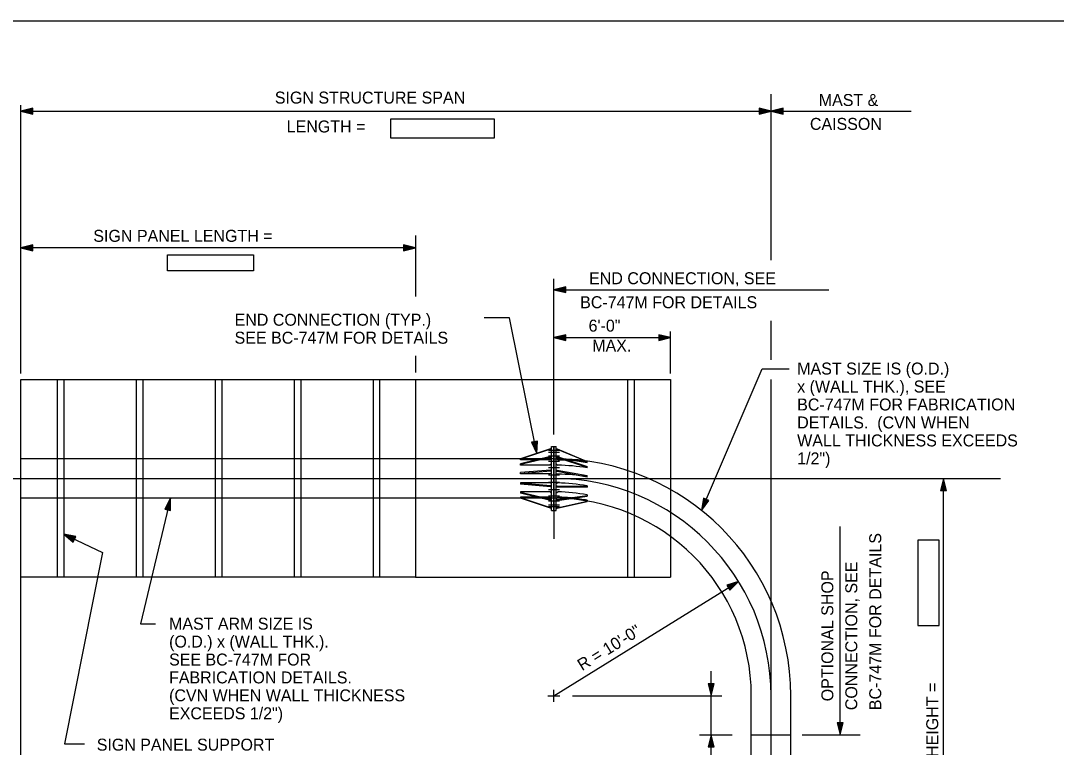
# Model space of a CAD drawing. Extents: x 640117 to 642655, y 297247 to 298435.
# Drawn here: x 640465.5 to 640724.9, y 297644.5 to 297826.5 of the extents above; entities that cross this region are included whole.
import ezdxf

# ---------------------------------------------------------------- set-up
doc = ezdxf.new("R2010")
doc.units = 0
for name, color, linetype in [('10', 7, 'Continuous'), ('2', 7, 'Continuous'), ('48', 7, 'Continuous'), ('49', 7, 'Continuous'), ('50', 7, 'Continuous'), ('52', 7, 'Continuous'), ('53', 7, 'Continuous'), ('55', 7, 'Continuous')]:
    doc.layers.add(name, color=color, linetype=linetype)

msp = doc.modelspace()

# ---------------------------------------------------------------- linework, layer by layer
at = {"layer": '10'}
msp.add_lwpolyline([(640690.25, 297675.07), (640695.62, 297675.07), (640695.62, 297696.4), (640690.25, 297696.4)], close=True, dxfattribs=at)
at = {"layer": '2'}
msp.add_line((640157.46, 297826.46), (640943.46, 297826.46), dxfattribs=at)
for points in [[(640558.23, 297801.89), (640584.08, 297801.89), (640584.08, 297797.09), (640558.23, 297797.09)], [(640502.27, 297767.87), (640523.82, 297767.87), (640523.82, 297763.87), (640502.27, 297763.87)]]:
    msp.add_lwpolyline(points, close=True, dxfattribs=at)
at = {"layer": '48'}
for p, q in [((640597.69, 297718.9), (640600.47, 297718.9)), ((640597.69, 297718.42), (640600.47, 297718.42)), ((640597.69, 297717.49), (640600.47, 297717.49)), ((640597.69, 297716.18), (640600.47, 297716.18)), ((640597.69, 297714.57), (640600.47, 297714.57)), ((640597.69, 297712.78), (640600.47, 297712.78)), ((640597.69, 297710.92), (640600.47, 297710.92)), ((640597.69, 297709.13), (640600.47, 297709.13)), ((640597.69, 297707.52), (640600.47, 297707.52)), ((640597.69, 297706.21), (640600.47, 297706.21)), ((640597.69, 297705.28), (640600.47, 297705.28)), ((640597.69, 297704.8), (640600.47, 297704.8))]:
    msp.add_line(p, q, dxfattribs=at)
at = {"layer": '49'}
for p, q in [((640465.5, 297736.59), (640564.44, 297736.59)), ((640465.5, 297687.12), (640465.5, 297736.59)), ((640474.63, 297736.59), (640474.63, 297687.12)), ((640476.28, 297736.59), (640476.28, 297687.12)), ((640494.42, 297736.59), (640494.42, 297687.12)), ((640496.06, 297736.59), (640496.06, 297687.12)), ((640514.2, 297736.59), (640514.2, 297687.12)), ((640515.85, 297736.59), (640515.85, 297687.12)), ((640533.99, 297736.59), (640533.99, 297687.12)), ((640535.64, 297736.59), (640535.64, 297687.12)), ((640553.78, 297736.59), (640553.78, 297687.12)), ((640555.43, 297736.59), (640555.43, 297687.12)), ((640564.44, 297736.59), (640564.44, 297687.12)), ((640564.44, 297736.59), (640628.33, 297736.59)), ((640617.56, 297736.59), (640617.56, 297687.12)), ((640619.21, 297736.59), (640619.21, 297687.12)), ((640628.33, 297736.59), (640628.33, 297687.12)), ((640564.44, 297687.12), (640465.5, 297687.12)), ((640564.44, 297687.12), (640628.33, 297687.12))]:
    msp.add_line(p, q, dxfattribs=at)
at = {"layer": '50'}
for p, q in [((640653.49, 297766.52), (640653.49, 297808.07)), ((640653.49, 297741.55), (640653.49, 297751.3)), ((640653.49, 297531.9), (640653.49, 297736.65)), ((640599.07, 297719.88), (640599.07, 297696.76)), ((640196.72, 297711.85), (640710.96, 297711.85))]:
    msp.add_line(p, q, dxfattribs=at)
msp.add_arc((640599.07, 297657.43), 54.42, 0, 89.9997, dxfattribs=at)
at = {"layer": '52'}
for p, q in [((640465.5, 297738.09), (640465.5, 297805.35)), ((640468.5, 297804.6), (640465.5, 297803.85)), ((640465.5, 297803.85), (640653.49, 297803.85)), ((640465.5, 297803.85), (640468.5, 297803.1)), ((640468.33, 297804.37), (640466.24, 297803.85)), ((640466.24, 297803.85), (640468.33, 297803.32)), ((640468.15, 297804.14), (640466.97, 297803.85)), ((640466.97, 297803.85), (640468.15, 297803.55)), ((640468.08, 297803.94), (640467.7, 297803.85)), ((640467.7, 297803.85), (640468.06, 297803.76)), ((640468.15, 297803.55), (640468.15, 297804.14)), ((640468.33, 297803.32), (640468.33, 297804.37)), ((640468.5, 297803.1), (640468.5, 297804.6)), ((640653.49, 297803.85), (640650.49, 297804.6)), ((640650.49, 297804.6), (640650.49, 297803.1)), ((640650.49, 297803.1), (640653.49, 297803.85)), ((640652.76, 297803.85), (640650.67, 297804.37)), ((640650.67, 297804.37), (640650.67, 297803.32)), ((640650.67, 297803.32), (640652.76, 297803.85)), ((640652.03, 297803.85), (640650.85, 297804.14)), ((640650.85, 297804.14), (640650.85, 297803.55)), ((640650.85, 297803.55), (640652.03, 297803.85)), ((640650.92, 297803.75), (640651.29, 297803.85)), ((640651.29, 297803.85), (640650.94, 297803.94)), ((640656.49, 297804.6), (640653.49, 297803.85)), ((640653.49, 297803.85), (640656.49, 297803.1)), ((640656.31, 297804.37), (640654.22, 297803.85)), ((640654.22, 297803.85), (640656.31, 297803.32)), ((640656.14, 297804.14), (640654.96, 297803.85)), ((640654.96, 297803.85), (640656.14, 297803.55)), ((640656.07, 297803.94), (640655.69, 297803.85)), ((640655.69, 297803.85), (640656.05, 297803.76)), ((640656.14, 297803.55), (640656.14, 297804.14)), ((640656.31, 297803.32), (640656.31, 297804.37)), ((640656.49, 297803.1), (640656.49, 297804.6)), ((640564.44, 297772.65), (640564.44, 297757.39)), ((640468.5, 297770.32), (640465.5, 297769.57)), ((640564.44, 297769.57), (640465.5, 297769.57)), ((640465.5, 297769.57), (640468.5, 297768.82)), ((640468.33, 297770.1), (640466.24, 297769.57)), ((640466.24, 297769.57), (640468.33, 297769.05)), ((640468.15, 297769.87), (640466.97, 297769.57)), ((640466.97, 297769.57), (640468.15, 297769.28)), ((640468.08, 297769.67), (640467.7, 297769.57)), ((640467.7, 297769.57), (640468.06, 297769.48)), ((640468.15, 297769.28), (640468.15, 297769.87)), ((640468.33, 297769.05), (640468.33, 297770.1)), ((640468.5, 297768.82), (640468.5, 297770.32)), ((640564.44, 297769.57), (640561.44, 297770.32)), ((640561.44, 297770.32), (640561.44, 297768.82)), ((640561.44, 297768.82), (640564.44, 297769.57)), ((640563.71, 297769.57), (640561.62, 297770.1)), ((640561.62, 297770.1), (640561.62, 297769.05)), ((640561.62, 297769.05), (640563.71, 297769.57)), ((640562.98, 297769.57), (640561.8, 297769.87)), ((640561.8, 297769.87), (640561.8, 297769.28)), ((640561.8, 297769.28), (640562.98, 297769.57)), ((640561.87, 297769.48), (640562.25, 297769.57)), ((640562.25, 297769.57), (640561.89, 297769.66)), ((640599.07, 297722.88), (640599.07, 297761.86)), ((640602.07, 297759.87), (640599.07, 297759.12)), ((640601.9, 297759.64), (640599.81, 297759.12)), ((640601.72, 297759.42), (640600.54, 297759.12)), ((640601.65, 297759.21), (640601.27, 297759.12)), ((640601.72, 297758.83), (640601.72, 297759.42)), ((640601.9, 297758.6), (640601.9, 297759.64)), ((640602.07, 297758.37), (640602.07, 297759.87)), ((640599.07, 297759.12), (640602.07, 297758.37)), ((640599.81, 297759.12), (640601.9, 297758.6)), ((640600.54, 297759.12), (640601.72, 297758.83)), ((640601.27, 297759.12), (640601.63, 297759.03)), ((640602.07, 297747.85), (640599.07, 297747.11)), ((640599.07, 297747.11), (640628.33, 297747.11)), ((640599.07, 297747.11), (640602.07, 297746.36)), ((640601.9, 297747.63), (640599.81, 297747.11)), ((640599.81, 297747.11), (640601.9, 297746.58)), ((640601.72, 297747.4), (640600.54, 297747.11)), ((640600.54, 297747.11), (640601.72, 297746.81)), ((640601.65, 297747.2), (640601.27, 297747.11)), ((640601.27, 297747.11), (640601.63, 297747.02)), ((640601.72, 297746.81), (640601.72, 297747.4)), ((640601.9, 297746.58), (640601.9, 297747.63)), ((640602.07, 297746.36), (640602.07, 297747.85)), ((640628.33, 297747.11), (640625.33, 297747.85)), ((640625.33, 297747.85), (640625.33, 297746.36)), ((640625.33, 297746.36), (640628.33, 297747.11)), ((640627.6, 297747.11), (640625.51, 297747.63)), ((640625.51, 297747.63), (640625.51, 297746.58)), ((640625.51, 297746.58), (640627.6, 297747.11)), ((640626.87, 297747.11), (640625.69, 297747.4)), ((640625.69, 297747.4), (640625.69, 297746.81)), ((640625.69, 297746.81), (640626.87, 297747.11)), ((640625.76, 297747.01), (640626.14, 297747.11)), ((640626.14, 297747.11), (640625.78, 297747.2)), ((640628.33, 297738.09), (640628.33, 297748.61)), ((640564.44, 297742.56), (640564.44, 297738.42)), ((640594.96, 297721.22), (640593.49, 297720.92)), ((640593.49, 297720.92), (640594.82, 297718.13)), ((640594.77, 297721), (640593.75, 297720.79)), ((640593.75, 297720.79), (640594.67, 297718.84)), ((640594.59, 297720.78), (640594.01, 297720.66)), ((640594.01, 297720.66), (640594.53, 297719.56)), ((640594.22, 297720.63), (640594.38, 297720.28)), ((640594.38, 297720.28), (640594.4, 297720.65)), ((640594.53, 297719.56), (640594.59, 297720.78)), ((640594.67, 297718.84), (640594.77, 297721)), ((640594.82, 297718.13), (640594.96, 297721.22)), ((640696.66, 297711.85), (640695.91, 297708.85)), ((640696.66, 297711.12), (640696.13, 297709.03)), ((640696.66, 297710.39), (640696.36, 297709.21)), ((640696.66, 297588.17), (640696.66, 297711.85)), ((640697.4, 297708.85), (640696.66, 297711.85)), ((640697.18, 297709.03), (640696.66, 297711.12)), ((640696.95, 297709.21), (640696.66, 297710.39)), ((640695.91, 297708.85), (640697.4, 297708.85)), ((640696.13, 297709.03), (640697.18, 297709.03)), ((640696.36, 297709.21), (640696.95, 297709.21)), ((640696.66, 297709.65), (640696.57, 297709.3)), ((640696.75, 297709.28), (640696.66, 297709.65)), ((640503.03, 297706.9), (640501.61, 297704.16)), ((640502.86, 297706.19), (640501.87, 297704.28)), ((640502.69, 297705.48), (640502.13, 297704.4)), ((640502.52, 297704.77), (640502.35, 297704.44)), ((640502.53, 297704.38), (640502.52, 297704.77)), ((640502.71, 297704.26), (640502.69, 297705.48)), ((640502.89, 297704.04), (640502.86, 297706.19)), ((640503.07, 297703.81), (640503.03, 297706.9)), ((640636.55, 297706.92), (640636.06, 297703.87)), ((640636.06, 297703.87), (640637.93, 297706.33)), ((640636.69, 297706.67), (640636.35, 297704.54)), ((640636.35, 297704.54), (640637.65, 297706.26)), ((640637.93, 297706.33), (640636.55, 297706.92)), ((640636.83, 297706.42), (640636.64, 297705.22)), ((640636.64, 297705.22), (640637.37, 297706.18)), ((640637.65, 297706.26), (640636.69, 297706.67)), ((640637.37, 297706.18), (640636.83, 297706.42)), ((640636.99, 297706.27), (640636.92, 297705.89)), ((640636.92, 297705.89), (640637.15, 297706.18)), ((640501.61, 297704.16), (640503.07, 297703.81)), ((640501.87, 297704.28), (640502.89, 297704.04)), ((640502.13, 297704.4), (640502.71, 297704.26)), ((640476.28, 297697.9), (640478.67, 297695.94)), ((640479.31, 297697.3), (640476.28, 297697.9)), ((640476.94, 297697.59), (640478.61, 297696.22)), ((640479.05, 297697.17), (640476.94, 297697.59)), ((640478.79, 297697.04), (640477.6, 297697.27)), ((640477.6, 297697.27), (640478.54, 297696.5)), ((640478.26, 297696.96), (640478.55, 297696.73)), ((640478.64, 297696.88), (640478.26, 297696.96)), ((640478.54, 297696.5), (640478.79, 297697.04)), ((640478.61, 297696.22), (640479.05, 297697.17)), ((640478.67, 297695.94), (640479.31, 297697.3)), ((640465.5, 297626.36), (640465.5, 297687.12)), ((640599.07, 297657.43), (640645.35, 297686.07)), ((640645.35, 297686.07), (640642.4, 297685.13)), ((640642.4, 297685.13), (640643.19, 297683.86)), ((640644.72, 297685.69), (640642.67, 297685.03)), ((640642.67, 297685.03), (640643.22, 297684.14)), ((640644.1, 297685.3), (640642.94, 297684.93)), ((640642.94, 297684.93), (640643.25, 297684.43)), ((640643.48, 297684.91), (640643.13, 297684.8)), ((640643.19, 297683.86), (640645.35, 297686.07)), ((640643.21, 297684.64), (640643.48, 297684.91)), ((640643.22, 297684.14), (640644.72, 297685.69)), ((640643.25, 297684.43), (640644.1, 297685.3)), ((640638.5, 297626.19), (640638.5, 297663.57)), ((640599.07, 297655.93), (640599.07, 297658.93)), ((640637.75, 297660.43), (640638.5, 297657.43)), ((640639.25, 297660.43), (640637.75, 297660.43)), ((640637.98, 297660.26), (640638.5, 297658.17)), ((640639.02, 297660.26), (640637.98, 297660.26)), ((640638.21, 297660.08), (640638.5, 297658.9)), ((640638.8, 297660.08), (640638.21, 297660.08)), ((640638.41, 297660.01), (640638.5, 297659.63)), ((640638.5, 297657.43), (640639.25, 297660.43)), ((640638.5, 297658.17), (640639.02, 297660.26)), ((640638.5, 297658.9), (640638.8, 297660.08)), ((640638.5, 297659.63), (640638.59, 297659.99)), ((640597.57, 297657.43), (640600.57, 297657.43)), ((640603.75, 297657.43), (640641.12, 297657.43)), ((640670.09, 297650.68), (640670.84, 297647.68)), ((640671.59, 297650.68), (640670.09, 297650.68)), ((640670.32, 297650.5), (640670.84, 297648.41)), ((640671.36, 297650.5), (640670.32, 297650.5)), ((640670.54, 297650.33), (640670.84, 297649.15)), ((640671.13, 297650.33), (640670.54, 297650.33)), ((640670.75, 297650.25), (640670.84, 297649.88)), ((640670.84, 297647.68), (640671.59, 297650.68)), ((640670.84, 297648.41), (640671.36, 297650.5)), ((640670.84, 297649.15), (640671.13, 297650.33)), ((640670.84, 297649.88), (640670.93, 297650.24)), ((640635.6, 297647.68), (640643.75, 297647.68)), ((640638.5, 297647.68), (640637.75, 297644.68)), ((640638.5, 297647.68), (640638.5, 297647.68)), ((640639.25, 297644.68), (640638.5, 297647.68)), ((640661.31, 297647.68), (640675.81, 297647.68)), ((640638.5, 297646.95), (640637.98, 297644.86)), ((640638.5, 297646.21), (640638.21, 297645.03)), ((640638.21, 297645.03), (640638.8, 297645.03)), ((640638.5, 297645.48), (640638.41, 297645.12)), ((640639.02, 297644.86), (640638.5, 297646.95)), ((640638.8, 297645.03), (640638.5, 297646.21)), ((640638.59, 297645.11), (640638.5, 297645.48)), ((640637.75, 297644.68), (640639.25, 297644.68)), ((640637.98, 297644.86), (640639.02, 297644.86))]:
    msp.add_line(p, q, dxfattribs=at)
for points in [[(640653.49, 297803.85), (640688.61, 297803.85)], [(640599.07, 297759.12), (640667.98, 297759.12)], [(640594.82, 297718.13), (640587.98, 297752.1), (640581.62, 297752.1)], [(640636.06, 297703.87), (640651.22, 297739.32), (640658.03, 297739.32)], [(640503.03, 297706.9), (640495.54, 297675.43), (640499.29, 297675.43)], [(640670.84, 297647.68), (640670.84, 297699.86)], [(640476.28, 297697.9), (640485.97, 297693.32), (640476.48, 297645.39), (640481.47, 297645.39)]]:
    msp.add_lwpolyline(points, dxfattribs=at)
at = {"layer": '55'}
for p, q in [((640598.26, 297719.25), (640590.74, 297716.8)), ((640598.26, 297719.17), (640590.74, 297716.72)), ((640598.46, 297719.25), (640598.26, 297719.25)), ((640598.46, 297719.17), (640598.26, 297719.17)), ((640598.46, 297719.88), (640599.68, 297719.88)), ((640598.46, 297703.82), (640598.46, 297719.88)), ((640599.07, 297703.82), (640599.07, 297719.88)), ((640599.68, 297703.82), (640599.68, 297719.88)), ((640599.68, 297719.25), (640599.89, 297719.25)), ((640599.68, 297719.17), (640599.89, 297719.17)), ((640599.89, 297719.25), (640607.4, 297716.14)), ((640599.89, 297719.17), (640607.4, 297716.06)), ((640564.44, 297716.8), (640465.5, 297716.8)), ((640599.07, 297716.8), (640564.44, 297716.8)), ((640598.26, 297717.35), (640590.74, 297715.55)), ((640598.26, 297717.13), (640590.74, 297715.33)), ((640590.74, 297716.52), (640590.74, 297716.8)), ((640590.74, 297716.73), (640598.46, 297716.73)), ((640594.81, 297716.52), (640590.74, 297716.52)), ((640590.74, 297715.19), (640590.74, 297715.55)), ((640598.06, 297715.19), (640590.74, 297715.19)), ((640598.06, 297716.52), (640594.81, 297716.52)), ((640598.46, 297716.91), (640598.06, 297716.52)), ((640598.46, 297715.48), (640598.06, 297715.19)), ((640598.46, 297717.35), (640598.26, 297717.35)), ((640598.46, 297717.13), (640598.26, 297717.13)), ((640599.68, 297717.35), (640599.89, 297717.35)), ((640599.68, 297717.13), (640599.89, 297717.13)), ((640599.68, 297716.91), (640600.09, 297716.52)), ((640599.68, 297715.48), (640600.09, 297715.19)), ((640599.89, 297717.35), (640607.4, 297714.88)), ((640599.89, 297717.13), (640607.4, 297714.66)), ((640600.09, 297716.52), (640603.34, 297716.52)), ((640603.34, 297716.52), (640607.4, 297715.87)), ((640607.4, 297715.87), (640607.4, 297716.14)), ((640598.26, 297713.97), (640590.74, 297713.31)), ((640598.26, 297713.68), (640590.74, 297713.02)), ((640590.74, 297712.97), (640590.74, 297713.31)), ((640598.06, 297712.97), (640590.74, 297712.97)), ((640598.46, 297713.07), (640598.06, 297712.97)), ((640598.46, 297713.97), (640598.26, 297713.97)), ((640598.46, 297713.68), (640598.26, 297713.68)), ((640599.68, 297713.97), (640599.89, 297713.97)), ((640599.68, 297713.68), (640599.89, 297713.68)), ((640599.68, 297713.07), (640600.09, 297712.97)), ((640599.89, 297713.97), (640607.4, 297712.56)), ((640599.89, 297713.68), (640607.4, 297712.27)), ((640607.4, 297714.52), (640607.4, 297714.88)), ((640607.4, 297712.21), (640607.4, 297712.56)), ((640590.74, 297710.74), (640590.74, 297710.39)), ((640598.06, 297710.74), (640590.74, 297710.74)), ((640598.26, 297710.03), (640590.74, 297710.68)), ((640598.26, 297709.73), (640590.74, 297710.39)), ((640598.46, 297710.63), (640598.06, 297710.74)), ((640598.46, 297710.03), (640598.26, 297710.03)), ((640599.68, 297710.63), (640600.09, 297710.74)), ((640599.68, 297710.03), (640599.89, 297710.03)), ((640599.89, 297710.03), (640607.4, 297709.95)), ((640607.4, 297710), (640607.4, 297709.66)), ((640590.74, 297708.51), (640590.74, 297708.15)), ((640598.06, 297708.51), (640590.74, 297708.51)), ((640598.26, 297706.57), (640590.74, 297708.37)), ((640598.26, 297706.36), (640590.74, 297708.15)), ((640598.46, 297708.22), (640598.06, 297708.51)), ((640598.46, 297709.73), (640598.26, 297709.73)), ((640599.68, 297709.73), (640599.89, 297709.73)), ((640599.68, 297708.22), (640600.09, 297708.51)), ((640599.89, 297709.73), (640607.4, 297709.66)), ((640599.89, 297706.57), (640607.4, 297707.6)), ((640599.89, 297706.36), (640607.4, 297707.38)), ((640607.4, 297707.74), (640607.4, 297707.38)), ((640564.44, 297706.9), (640465.5, 297706.9)), ((640599.07, 297706.9), (640564.44, 297706.9)), ((640590.74, 297707.18), (640590.74, 297706.91)), ((640594.81, 297707.18), (640590.74, 297707.18)), ((640598.26, 297704.53), (640590.74, 297706.99)), ((640590.74, 297706.97), (640598.46, 297706.97)), ((640598.26, 297704.45), (640590.74, 297706.91)), ((640598.06, 297707.18), (640594.81, 297707.18)), ((640598.46, 297706.79), (640598.06, 297707.18)), ((640598.46, 297706.57), (640598.26, 297706.57)), ((640598.46, 297706.36), (640598.26, 297706.36)), ((640599.68, 297706.79), (640600.09, 297707.18)), ((640599.68, 297706.57), (640599.89, 297706.57)), ((640599.68, 297706.36), (640599.89, 297706.36)), ((640599.89, 297704.53), (640607.4, 297706.19)), ((640599.89, 297704.45), (640607.4, 297706.11)), ((640607.4, 297706.39), (640607.4, 297706.11)), ((640598.46, 297704.53), (640598.26, 297704.53)), ((640598.46, 297704.45), (640598.26, 297704.45)), ((640598.46, 297703.82), (640599.68, 297703.82)), ((640599.68, 297704.53), (640599.89, 297704.53)), ((640599.68, 297704.45), (640599.89, 297704.45)), ((640648.54, 297601.81), (640648.54, 297657.43)), ((640658.44, 297601.81), (640658.44, 297657.43)), ((640648.54, 297647.68), (640658.44, 297647.68))]:
    msp.add_line(p, q, dxfattribs=at)
for centre, radius, start, end in [((640599.07, 297657.43), 59.36, 0, 90), ((640599.07, 297663.08), 53.64, 81.0656, 90), ((640599.07, 297663.08), 53.44, 81.031, 88.9106), ((640599.07, 297663.08), 52.11, 80.8, 88.8828), ((640599.07, 297663.08), 49.88, 80.3857, 88.833), ((640599.07, 297663.08), 47.65, 79.9312, 88.7783), ((640599.07, 297663.08), 45.43, 79.4324, 88.7185), ((640599.07, 297663.08), 43.89, 79.058, 90), ((640599.07, 297657.43), 49.47, 0, 90), ((640599.07, 297663.08), 44.1, 83.6558, 88.6798), ((640599.07, 297663.08), 44.1, 79.1097, 83.6558)]:
    msp.add_arc(centre, radius, start, end, dxfattribs=at)

# ---------------------------------------------------------------- texts
at = {"layer": '10'}
for s, height, p in [('  MAST &', 2.992, (640663.23, 297805.11)), ('CAISSON', 2.992, (640663.23, 297799.13)), ('MAST ARM SIZE IS', 2.9917, (640502.68, 297674)), ('(O.D.) x (WALL THK.).', 2.9917, (640502.68, 297669.51)), ('SEE BC-747M FOR', 2.9917, (640502.68, 297665.02)), ('FABRICATION DETAILS.', 2.9917, (640502.68, 297660.54)), ('(CVN WHEN WALL THICKNESS', 2.9917, (640502.68, 297656.05)), ('EXCEEDS 1/2")', 2.9917, (640502.68, 297651.56)), ('SIGN PANEL SUPPORT', 2.9917, (640484.56, 297643.71))]:
    msp.add_text(s, height=height, dxfattribs=at).set_placement(p)
at = {"layer": '2'}
for s, p in [('  END CONNECTION, SEE', (640605.66, 297760.48)), ('BC-747M FOR DETAILS ', (640605.66, 297754.48)), ('END CONNECTION (TYP.)', (640519.08, 297750.09)), ('SEE BC-747M FOR DETAILS', (640519.08, 297745.59)), ('MAST SIZE IS (O.D.)', (640660.03, 297737.87)), ('x (WALL THK.), SEE', (640660.03, 297733.37)), ('BC-747M FOR FABRICATION', (640660.03, 297728.87)), ('DETAILS.  (CVN WHEN', (640660.03, 297724.37)), ('WALL THICKNESS EXCEEDS', (640660.03, 297719.87)), ('1/2")', (640660.03, 297715.37))]:
    msp.add_text(s, height=3, dxfattribs=at).set_placement(p)
for s, rotation, p in [('BC-747M FOR DETAILS', 90, (640681.09, 297653.83)), ('CONNECTION, SEE', 90, (640675.09, 297653.83)), ('  OPTIONAL SHOP', 90, (640669.09, 297653.83)), ('R = 10\'-0"', 31.7534, (640606.15, 297663.58)), ('SIGN STRUCTURE HEIGHT =', 90, (640695.37, 297605.34))]:
    msp.add_text(s, height=3, rotation=rotation, dxfattribs=at).set_placement(p)
at = {"layer": '52'}
for s, p in [('SIGN STRUCTURE SPAN', (640529.16, 297805.71)), ('LENGTH =', (640532.13, 297798.48)), ('6\'-0"', (640607.77, 297748.61))]:
    msp.add_text(s, height=3, dxfattribs=at).set_placement(p)
at = {"layer": '53'}
for s, p in [('SIGN PANEL LENGTH =', (640483.69, 297771.1)), ('MAX.', (640608.68, 297743.6))]:
    msp.add_text(s, height=3, dxfattribs=at).set_placement(p)

doc.saveas('drawing.dxf')
